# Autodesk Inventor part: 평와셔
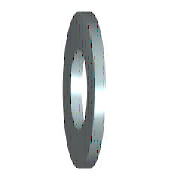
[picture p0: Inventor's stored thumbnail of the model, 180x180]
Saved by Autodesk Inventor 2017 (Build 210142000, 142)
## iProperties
Created: 2012-02
Part Number: 평와셔
Material: 강철
Description: 평면 와셔 - 초대형 시리즈 - 제품 등급 C
Document SubType Name: Modeling
Standard: ISO 7094
Designer: mduedu
Standard Revision: Second edition 2000-06-01
Standards Organization: ISO
Language: ko-KR
Size Designation: ST 5 - 100 HV
Categories: <MemberInstance><Categories><Category DisplayName="조임쇠" InternalName="e4da775c-781d-43d5-af7c-5136215cf5a6" Mnemonic="FSTN"><Category DisplayName="와셔" InternalN
Density: 7.85 g/cm^3
Appearance: 파란색 - 벽 페인트 - 광택
Mass: 3.62216 g
Surface Area: 6.09076 cm^2
Volume: 0.461421 cm^3
IsCustomPart: 1
Author: mduedu
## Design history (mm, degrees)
sketch "스케치"
  geometry: C1 r 9 at (0, 0); C2 r 2.75 at (0, 0); 1 further point
  constraints: 2 centre point, 2 coincident
  dimensions: "d0" = 5.5 diameter of C2 (= SD1); "d1" = 18 diameter of C1 (= SD2)
extrude "본체" new body sketch "스케치" distance "d2" = 2 (= SD); taper "d3" = 0 deg
workaxis "Work Axis1"
workplane "Work Plane1"
body "Solid1"
other parameters: "SD1" = 5.5 [user parameter; used in 1 equation term], "SD2" = 18 [user parameter; used in 1 equation term], "SD" = 2 [user parameter; used in 1 equation term], "d4" = 0, "d5" = 0, "d6" = 0, "d7" = 0, "NND" = 5 [user parameter]
